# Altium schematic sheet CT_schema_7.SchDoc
size 479 x 328 mm
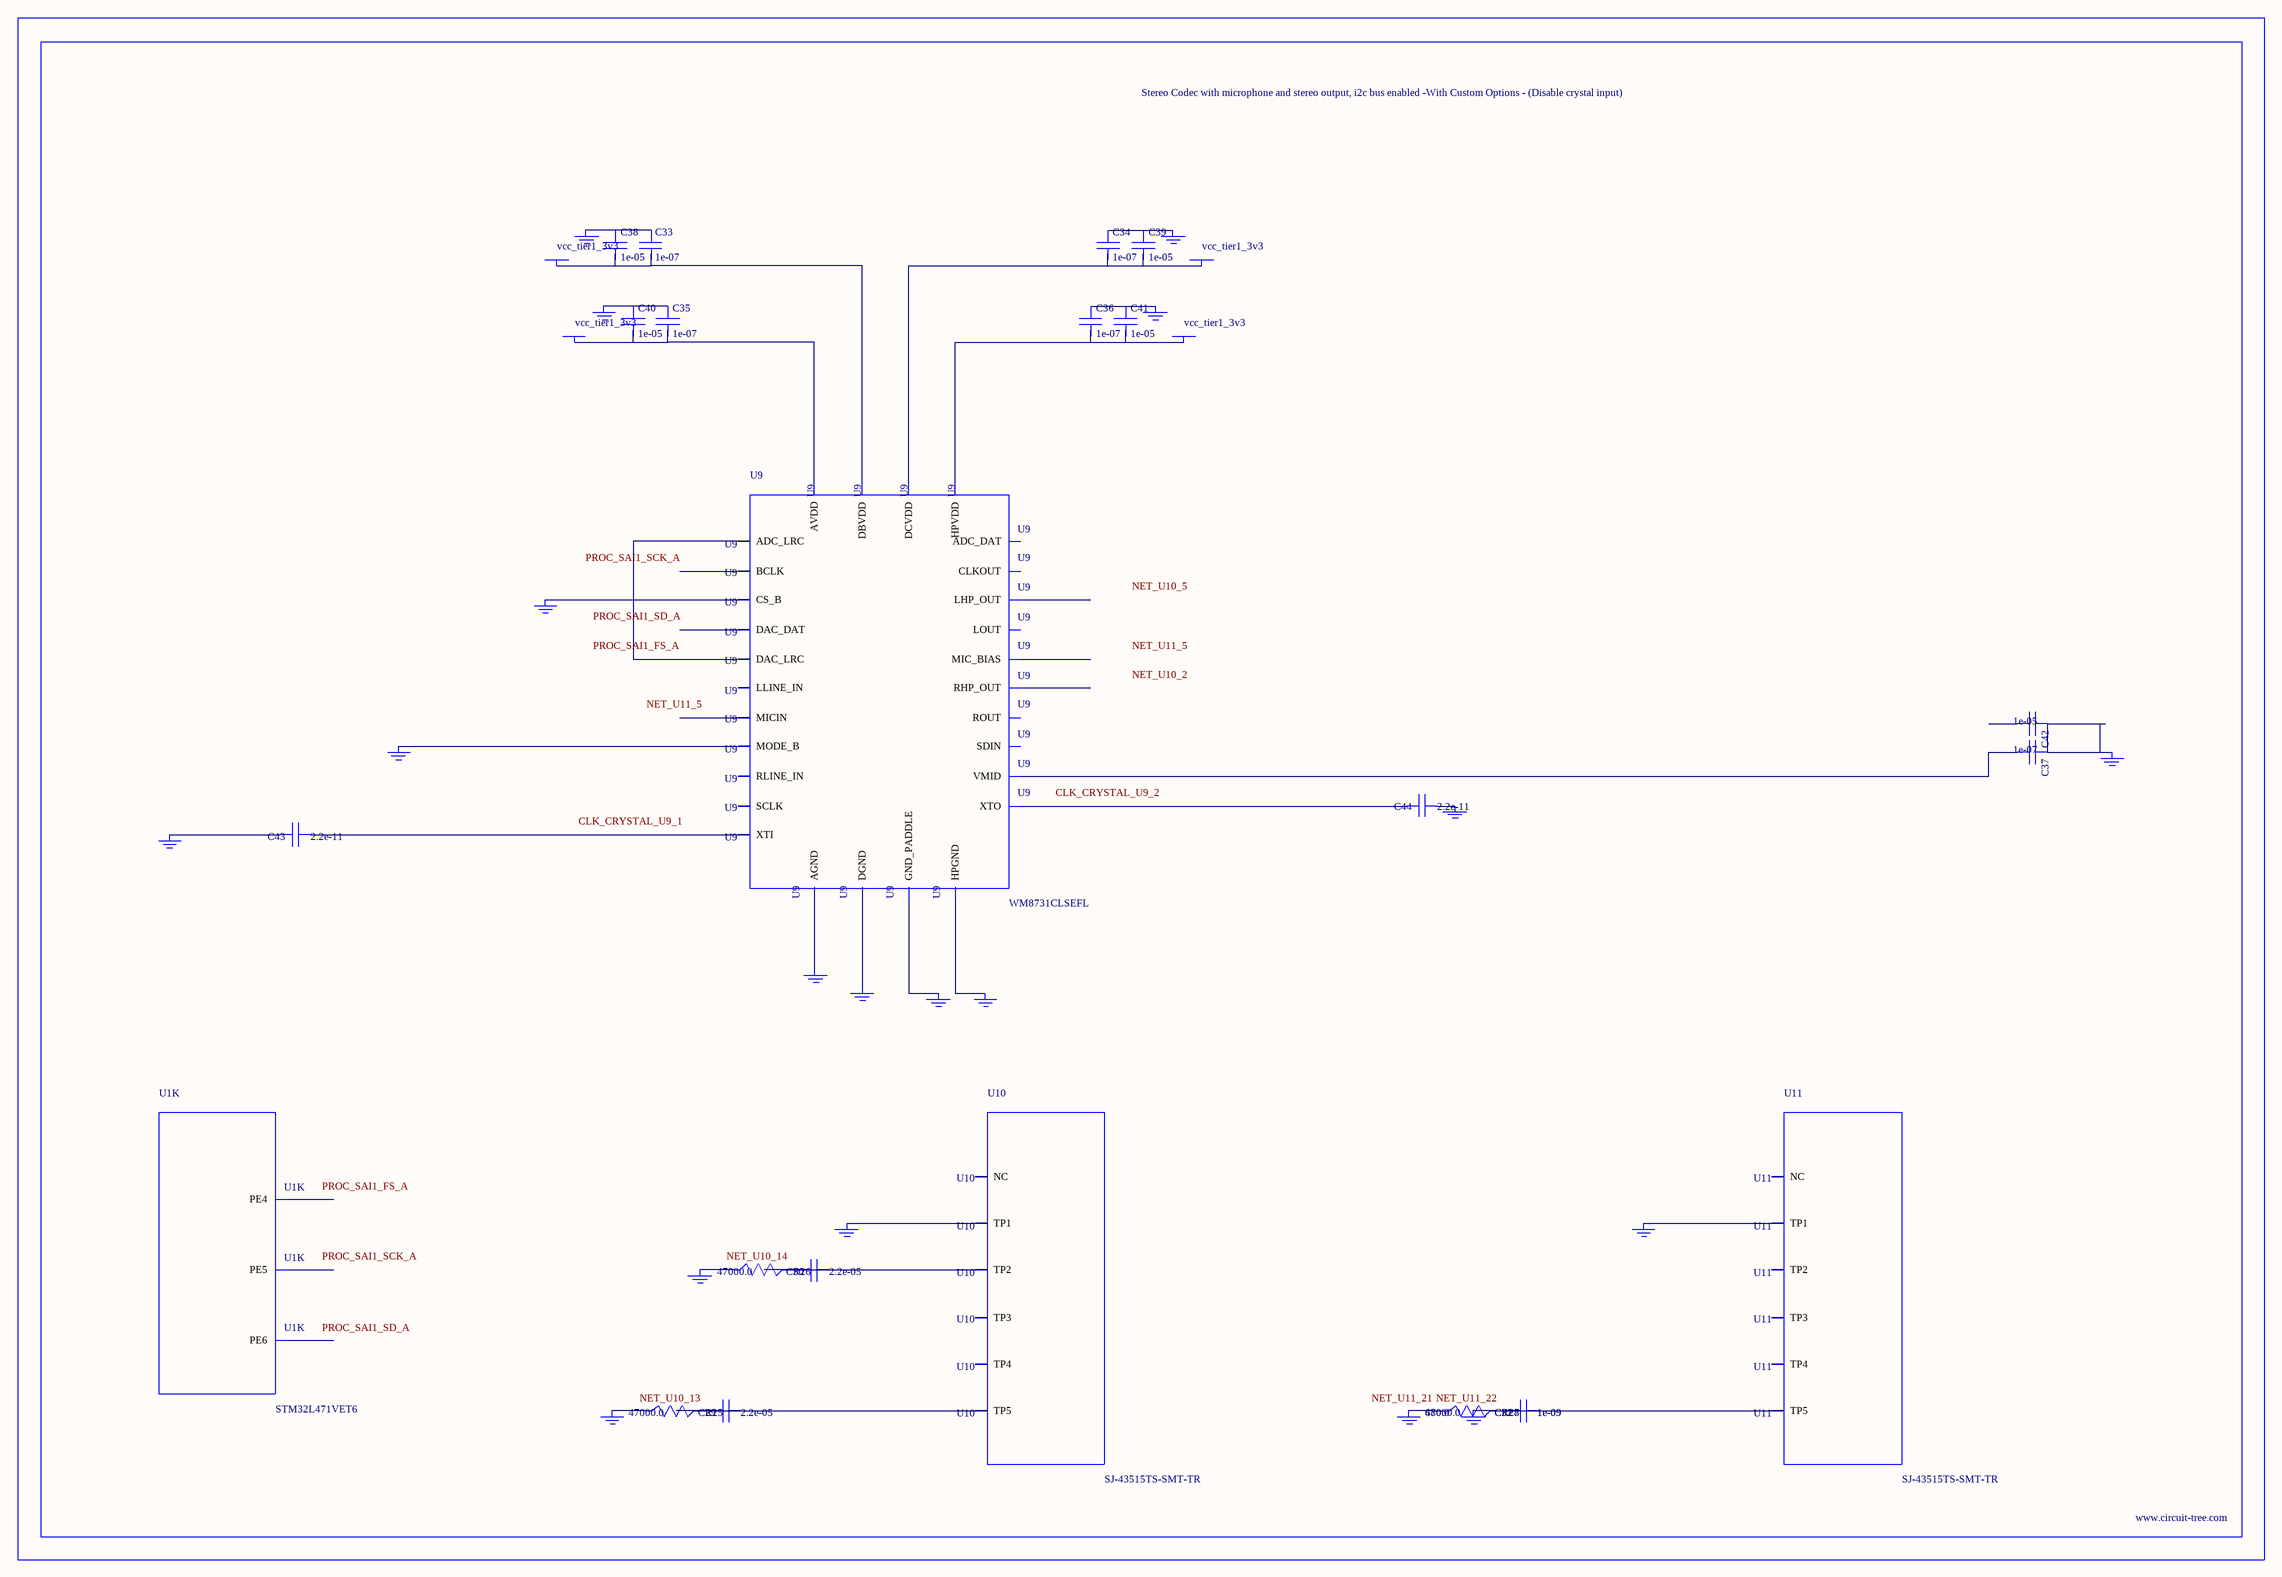
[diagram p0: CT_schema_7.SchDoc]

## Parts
BORDER6  (no value)
C29  2.2e-05  [C1210]
C30  2.2e-05  [C1210]
C31  1e-09  [C0402]
C32  1e-09  [C0402]
C33  1e-07  [C0402]
C34  1e-07  [C0402]
C35  1e-07  [C0402]
C36  1e-07  [C0402]
C37  1e-07  [C0402]
C38  1e-05  [C0805]
C39  1e-05  [C0805]
C40  1e-05  [C0805]
C41  1e-05  [C0805]
C42  1e-05  [C0805]
C43  2.2e-11  [C0402]
C44  2.2e-11  [C0402]
GND_INSTANCE_6_0  (no value)
GND_INSTANCE_6_1  (no value)
GND_INSTANCE_6_2  (no value)
GND_INSTANCE_6_3  (no value)
GND_INSTANCE_6_4  (no value)
GND_INSTANCE_6_5  (no value)
GND_INSTANCE_6_6  (no value)
GND_INSTANCE_6_7  (no value)
GND_INSTANCE_6_8  (no value)
GND_INSTANCE_6_9  (no value)
GND_INSTANCE_6_10  (no value)
GND_INSTANCE_6_11  (no value)
GND_INSTANCE_6_12  (no value)
GND_INSTANCE_6_13  (no value)
GND_INSTANCE_6_14  (no value)
GND_INSTANCE_6_15  (no value)
GND_INSTANCE_6_16  (no value)
GND_INSTANCE_6_17  (no value)
GND_INSTANCE_6_18  (no value)
POWER_INSTANCE_6_0  vcc_tier1_3v3
POWER_INSTANCE_6_1  vcc_tier1_3v3
POWER_INSTANCE_6_2  vcc_tier1_3v3
POWER_INSTANCE_6_3  vcc_tier1_3v3
R25  47000.0  [R0603]
R26  47000.0  [R0603]
R27  47000.0  [R0603]
R28  680.0  [R0603]
U1  STM32L471VET6  [LQFP100]  (part K of 11)
U9  WM8731CLSEFL  [QFN-28]
U10  SJ-43515TS-SMT-TR  [SJ-43515TS-SMT-TR]
U11  SJ-43515TS-SMT-TR  [SJ-43515TS-SMT-TR]

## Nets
NetC29_1: C29.1 C29.2 R25.2 U10.5(TP5)
NetC30_1: C30.1 C30.2 R26.2 U10.2(TP2)
NetC31_1: C31.1 C31.2 C32.1 C32.2 GND_INSTANCE_6_18.0(GND) R27.2 R28.2 U11.5(TP5)
NetC33_1: C33.1 C38.1 GND_INSTANCE_6_3.0(GND)
NetC33_2: C33.2 C38.2 POWER_INSTANCE_6_1.0(PWR) U9.5(DBVDD)
NetC34_1: C34.1 C39.1 GND_INSTANCE_6_2.0(GND)
NetC34_2: C34.2 C39.2 POWER_INSTANCE_6_0.0(PWR) U9.3(DCVDD)
NetC35_1: C35.1 C40.1 GND_INSTANCE_6_6.0(GND)
NetC35_2: C35.2 C40.2 POWER_INSTANCE_6_3.0(PWR) U9.18(AVDD)
NetC36_1: C36.1 C41.1 GND_INSTANCE_6_4.0(GND)
NetC36_2: C36.2 C41.2 POWER_INSTANCE_6_2.0(PWR) U9.12(HPVDD)
NetC37_1: C37.1 C42.1 GND_INSTANCE_6_7.0(GND)
NetC37_2: C37.2 U9.20(VMID)
NetC43_1: C43.1 U9.1(XTI)
NetC43_2: C43.2 GND_INSTANCE_6_0.0(GND)
NetC44_1: C44.1 GND_INSTANCE_6_1.0(GND)
NetC44_2: C44.2 U9.2(XTO)
NetGND_INSTANCE_6_5_0: GND_INSTANCE_6_5.0(GND) U9.15(HPGND)
NetGND_INSTANCE_6_8_0: GND_INSTANCE_6_8.0(GND) U9.25(MODE_B)
NetGND_INSTANCE_6_9_0: GND_INSTANCE_6_9.0(GND) U9.26(CS_B)
NetGND_INSTANCE_6_10_0: GND_INSTANCE_6_10.0(GND) U9.29(GND_PADDLE)
NetGND_INSTANCE_6_11_0: GND_INSTANCE_6_11.0(GND) U9.4(DGND)
NetGND_INSTANCE_6_12_0: GND_INSTANCE_6_12.0(GND) U9.19(AGND)
NetGND_INSTANCE_6_13_0: GND_INSTANCE_6_13.0(GND) U10.1(TP1)
NetGND_INSTANCE_6_14_0: GND_INSTANCE_6_14.0(GND) R26.1
NetGND_INSTANCE_6_15_0: GND_INSTANCE_6_15.0(GND) R25.1
NetGND_INSTANCE_6_16_0: GND_INSTANCE_6_16.0(GND) U11.1(TP1)
NetGND_INSTANCE_6_17_0: GND_INSTANCE_6_17.0(GND) R27.1 R28.1
NetU9_9: U9.9(DAC_LRC) U9.11(ADC_LRC)

Not connected (* = marked no-connect by the designer): C42 2; U1 3(PE4) 4(PE5) 5(PE6); U9 6(CLKOUT) 7(BCLK) 8(DAC_DAT) 10(ADC_DAT) 13(LHP_OUT) 14(RHP_OUT) 16(LOUT) 17(ROUT) 21(MIC_BIAS) 22(MICIN) 23(RLINE_IN) 24(LLINE_IN) 27(SDIN) 28(SCLK); U10 3(TP3) 4(TP4) 6(NC); U11 2(TP2) 3(TP3) 4(TP4) 6(NC)

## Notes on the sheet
- Labels drawn without touching a wire or pin: CLK_CRYSTAL_U9_1, CLK_CRYSTAL_U9_2, NET_U10_2, NET_U10_5, NET_U10_13, NET_U10_14, NET_U11_5, NET_U11_21, NET_U11_22, PROC_SAI1_FS_A, PROC_SAI1_SCK_A, PROC_SAI1_SD_A

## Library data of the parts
BORDER6 = BORDER_PAGE6
C29 C30 = C1210C224K5RACTU
C31 C32 = C0402C102K3RAC
C33-C37 = C0402C104K3RACTU
C38-C42 = C0805C106K8RACTU
C43 C44 = C0402C220K3RAC
GND_INSTANCE_6_0-GND_INSTANCE_6_18 = GND
POWER_INSTANCE_6_0-POWER_INSTANCE_6_3 = PWR
R25-R27 = RC0603JR-0747KL
R28 = RC0603JR-07680RL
